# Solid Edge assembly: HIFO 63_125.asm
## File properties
Title: Zylinder
Author: ahadarics
Template: iso assembly.asm
Last saved by: ahadarics
Revision: 38
Application: Solid Edge
Username: ahadarics
Dokumentum tartalom típus: 1
Document Number: HIFO 63/125
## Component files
Kit_2.par
Kit_1.par
Profilrohr 63_125.par
Kolbenstange 63_125.par
Mutter.par
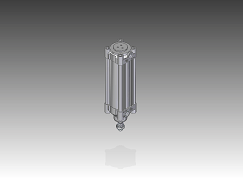
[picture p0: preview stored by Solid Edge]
